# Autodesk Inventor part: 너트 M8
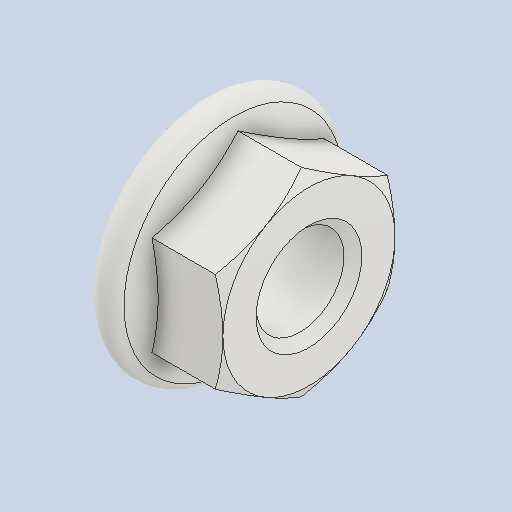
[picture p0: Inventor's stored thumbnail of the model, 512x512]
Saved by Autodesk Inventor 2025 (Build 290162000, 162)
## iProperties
Created: 2025-08
Part Number: 너트 M8
Material: 스테인리스강
Description: 플랜지붙이 6각 너트 - 일반 스레드
Document SubType Name: Modeling
Designer: infra017
Density: 8 g/cm^3
Appearance: 기본값
Author: jhkim
Sending System: Autodesk Inventor 2026
Preprocessor: ST-DEVELOPER v20.1
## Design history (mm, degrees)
feature "Solid1"
node "솔리드1"
